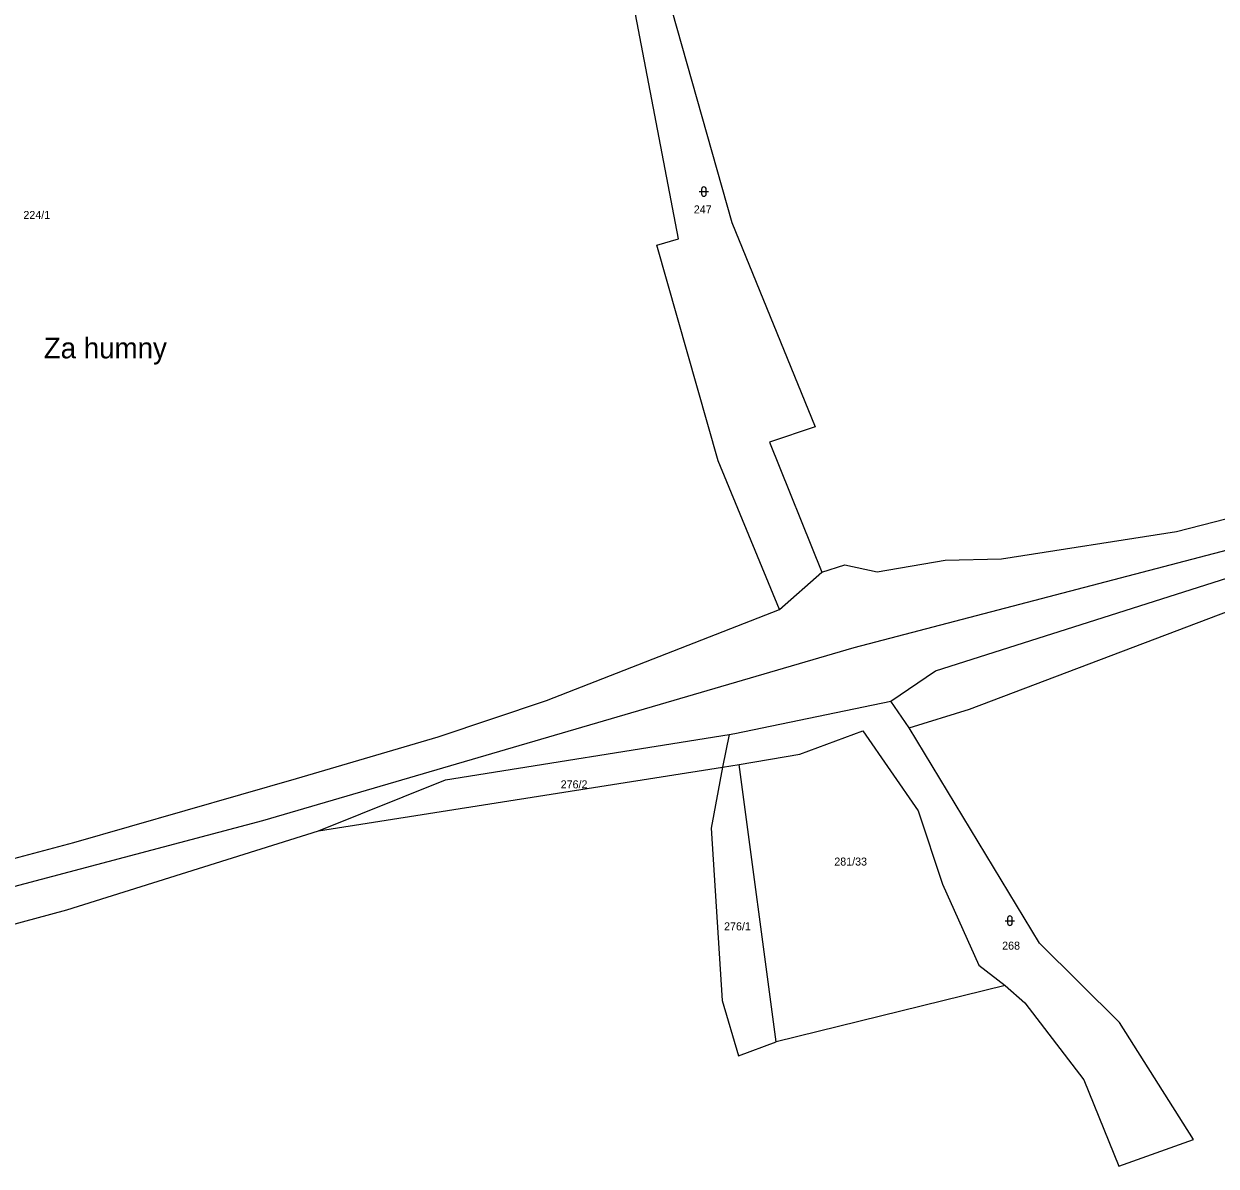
# Model space of a CAD drawing. Extents: x -779723 to -777378, y -1011169 to -1009297.
# Drawn here: x -778661.4 to -778408, y -1010420 to -1010177.3 of the extents above; entities that cross this region are included whole.
import ezdxf

# ---------------------------------------------------------------- set-up
doc = ezdxf.new("R2010")
doc.units = 0
for name, color, linetype in [('Hranice parcel', 7, 'Continuous'), ('Parcelní čísla', 7, 'Continuous'), ('Pop  PČ popisy', 7, 'Continuous'), ('Poz předměty', 7, 'Continuous'), ('Značky kultur', 7, 'Continuous')]:
    doc.layers.add(name, color=color, linetype=linetype)

msp = doc.modelspace()

# ---------------------------------------------------------------- linework, layer by layer
at = {"layer": 'Hranice parcel'}
for p, q in [((-778500.81, -1010301.69), (-778491.82, -1010293.76)), ((-778473.29, -1010326.85), (-778477.19, -1010321.19)), ((-778511.55, -1010328.28), (-778512.93, -1010335.18)), ((-778512.93, -1010335.18), (-778509.43, -1010334.65)), ((-778501.51, -1010393.56), (-778509.43, -1010334.65)), ((-778598.81, -1010348.7), (-778512.93, -1010335.18)), ((-778452.86, -1010381.6), (-778501.51, -1010393.56))]:
    msp.add_line(p, q, dxfattribs=at)
for points in [[(-778500.81, -1010301.69), (-778513.85, -1010270.13), (-778526.89, -1010224.31), (-778522.27, -1010222.95), (-778532.06, -1010171.83), (-778539.76, -1010139.89), (-778544.84, -1010111.19), (-778541.98, -1010100.57), (-778542.87, -1010088.3), (-778547.31, -1010081.95), (-778547.93, -1010079.4), (-778552.26, -1010061.45), (-778550.67, -1010051.95), (-778554.23, -1010046.82)], [(-778543.3, -1010047.94), (-778546.71, -1010062.28), (-778542.32, -1010080.9), (-778538.43, -1010086.26), (-778536.83, -1010100.87), (-778537.2, -1010135.97), (-778524.77, -1010170.64), (-778510.96, -1010219.51), (-778493.25, -1010262.91), (-778502.97, -1010266.15), (-778491.82, -1010293.76)], [(-778491.82, -1010293.76), (-778486.94, -1010292.24), (-778480.1, -1010293.71), (-778465.61, -1010291.22), (-778453.63, -1010290.98), (-778416.45, -1010285.13), (-778355.22, -1010269.42), (-778205.12, -1010236.96), (-778171.83, -1010233.51), (-778124.65, -1010234.94), (-778031.73, -1010232.44), (-777963.69, -1010234.58), (-777916.19, -1010237.79), (-777862.6, -1010242.68), (-777843.18, -1010245), (-777757.95, -1010256.86)], [(-778477.19, -1010321.19), (-778467.71, -1010314.76), (-778368.39, -1010283.19), (-778286.02, -1010267.72), (-778238.51, -1010262.52), (-778183.15, -1010258.35)], [(-778473.29, -1010326.85), (-778460.45, -1010322.86), (-778400.28, -1010300.05), (-778324.08, -1010280.87), (-778286.91, -1010275.41), (-778253.85, -1010272.28), (-778193.74, -1010270.34)], [(-778738.09, -1010373.73), (-778703.98, -1010365.37), (-778650.77, -1010351.2), (-778603.44, -1010337.58), (-778573.36, -1010328.79), (-778550.31, -1010321.04), (-778500.81, -1010301.69)], [(-778511.55, -1010328.28), (-778510.29, -1010328.03), (-778477.19, -1010321.19)], [(-778452.86, -1010381.6), (-778448.7, -1010385.27), (-778436.16, -1010401.64), (-778428.76, -1010419.95), (-778412.85, -1010414.3), (-778428.61, -1010389.44), (-778445.56, -1010372.62), (-778473.29, -1010326.85)], [(-778598.81, -1010348.7), (-778571.77, -1010337.89), (-778511.55, -1010328.28)], [(-778509.43, -1010334.65), (-778496.48, -1010332.41), (-778483.13, -1010327.49), (-778471.36, -1010344.5), (-778466.21, -1010360.03), (-778458.48, -1010377.24), (-778452.86, -1010381.6)], [(-778512.93, -1010335.18), (-778515.35, -1010348.17), (-778513.04, -1010384.74), (-778509.52, -1010396.54), (-778501.51, -1010393.56)], [(-778788.69, -1010399.25), (-778779.77, -1010391.5), (-778713.61, -1010376.07), (-778703.11, -1010376.44), (-778678, -1010372.43), (-778652.28, -1010365.5), (-778598.81, -1010348.7)]]:
    msp.add_lwpolyline(points, dxfattribs=at)
at = {"layer": 'Poz předměty'}
for p, q in [((-778485, -1010309.77), (-778348.82, -1010274.15)), ((-778610.59, -1010346.52), (-778485, -1010309.77)), ((-778682.94, -1010365.64), (-778610.59, -1010346.52))]:
    msp.add_line(p, q, dxfattribs=at)
at = {"layer": 'Značky kultur'}
for p, q in [((-778517.9, -1010212.94), (-778515.9, -1010212.94)), ((-778517.4, -1010212.44), (-778517.4, -1010213.44)), ((-778516.4, -1010213.44), (-778516.4, -1010212.44)), ((-778452.87, -1010367.81), (-778450.87, -1010367.81)), ((-778452.37, -1010367.31), (-778452.37, -1010368.31)), ((-778451.37, -1010368.31), (-778451.37, -1010367.31))]:
    msp.add_line(p, q, dxfattribs=at)
for centre, start, end in [((-778516.9, -1010212.44), 0, 180), ((-778516.9, -1010213.44), 180, 359.9879), ((-778451.87, -1010367.31), 0, 180), ((-778451.87, -1010368.31), 180, 359.9879)]:
    msp.add_arc(centre, 0.5, start, end, dxfattribs=at)

# ---------------------------------------------------------------- texts
at = {"layer": 'Parcelní čísla'}
for s, p in [('224/1', (-778661.5, -1010218.75)), ('247', (-778519.04, -1010217.57)), ('276/2', (-778547.33, -1010339.7)), ('281/33', (-778489.19, -1010356.1)), ('276/1', (-778512.61, -1010369.86)), ('268', (-778453.52, -1010373.96))]:
    msp.add_text(s, height=1.7, dxfattribs=at).set_placement(p)
at = {"layer": 'Pop  PČ popisy'}
msp.add_text('Za humny', height=4.4, dxfattribs=at).set_placement((-778657.17, -1010248.36))

doc.saveas('drawing.dxf')
